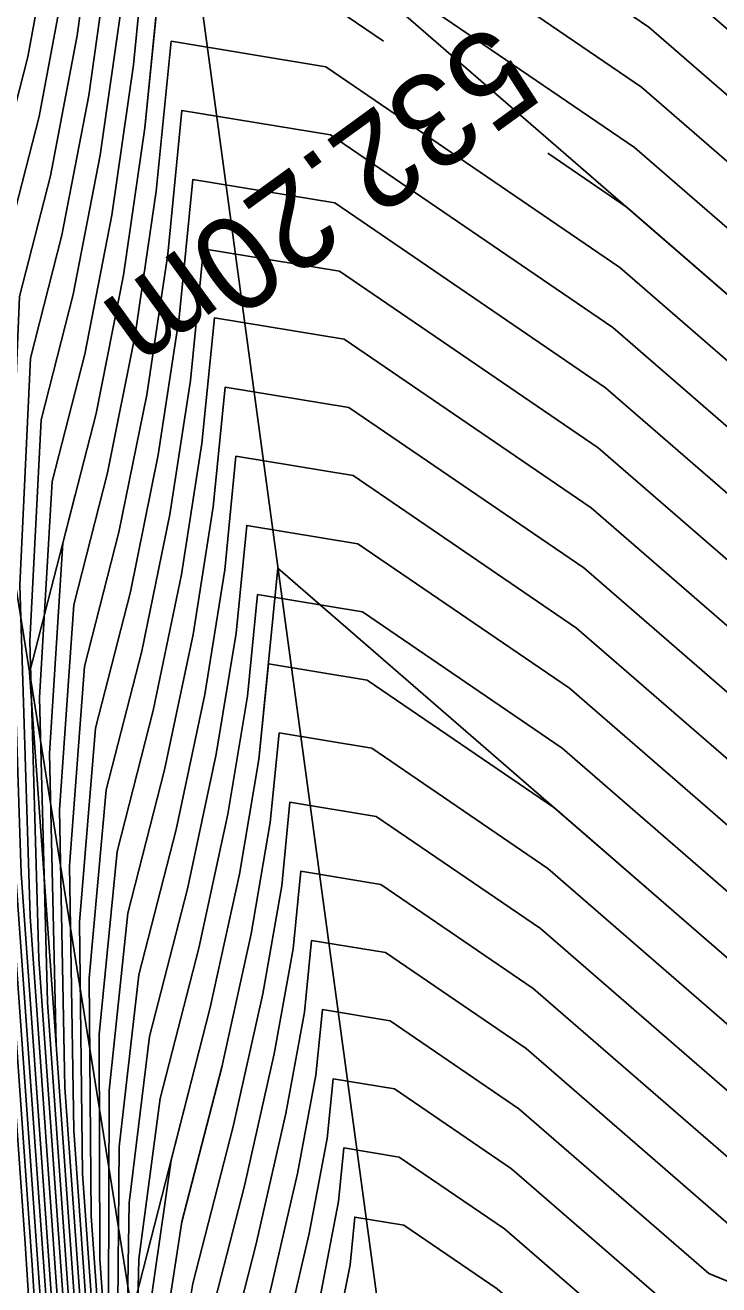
# Model space of a CAD drawing. Extents: x -866683 to -866410, y -1041951 to -1040252.
# Drawn here: x -866464.336 to -866462.114, y -1041913.857 to -1041909.824 of the extents above; entities that cross this region are included whole.
import ezdxf

# ---------------------------------------------------------------- set-up
doc = ezdxf.new("R2010")
doc.units = 0
for name, color, linetype in [('BREAKLINE', 7, 'Continuous'), ('V-VEDL', 7, 'Continuous'), ('V_po_cm', 7, 'Continuous')]:
    doc.layers.add(name, color=color, linetype=linetype)

msp = doc.modelspace()

# ---------------------------------------------------------------- linework, layer by layer
at = {"layer": 'BREAKLINE'}
for points in [[(-866488.573, -1041881.791), (-866474.022, -1041889.87), (-866470.477, -1041891.508), (-866467.312, -1041894.734), (-866465.316, -1041898.37), (-866463.007, -1041915.39), (-866458.763, -1041945.697)], [(-866461.505, -1041933.103), (-866461.806, -1041928.832), (-866463.744, -1041915.502), (-866466.191, -1041900.225), (-866466.769, -1041897.87), (-866468.011, -1041895.26), (-866470.525, -1041893.498), (-866471.281, -1041892.954)]]:
    msp.add_lwpolyline(points, dxfattribs=at)
at = {"layer": 'V-VEDL'}
for points in [[(-866464.3213, -1041911.8978), (-866464.1083, -1041911.0673), (-866464.0207, -1041910.6241), (-866463.9521, -1041910.153), (-866463.8529, -1041909.155)], [(-866456.0139, -1041911.9987), (-866456.2926, -1041911.9417), (-866456.7284, -1041912.0338), (-866457.4606, -1041912.2465), (-866458.4892, -1041912.5798), (-866459.6567, -1041912.3845), (-866460.9629, -1041911.6604), (-866463.8529, -1041909.155)], [(-866463.5263, -1041911.5623), (-866463.5872, -1041912.175), (-866463.6493, -1041912.542), (-866463.7429, -1041912.9695), (-866463.9933, -1041913.9456)], [(-866453.6171, -1041916.4043), (-866455.6514, -1041914.0403), (-866456.43, -1041913.2461), (-866456.9701, -1041912.8398), (-866457.2717, -1041912.8213), (-866457.8386, -1041912.9275), (-866458.6706, -1041913.1584), (-866459.7678, -1041913.5139), (-866460.795, -1041913.4946), (-866461.7521, -1041913.1004), (-866463.5263, -1041911.5623)], [(-866464.3213, -1041911.8978), (-866464.1509, -1041914.28), (-866464.0543, -1041915.8336), (-866463.9464, -1041917.7497), (-866463.8271, -1041920.0282), (-866463.661, -1041922.6795), (-866463.4481, -1041925.7036), (-866462.9286, -1041932.4974)]]:
    msp.add_lwpolyline(points, dxfattribs=at)
at = {"layer": 'V_po_cm'}
for points in [[(-866463.994, -1041919.6179), (-866464.1029, -1041917.5376), (-866464.2169, -1041915.5731), (-866464.3358, -1041913.7246), (-866464.4598, -1041911.992), (-866464.5119, -1041910.718), (-866464.4922, -1041909.9025), (-866464.4006, -1041909.5456), (-866464.3179, -1041909.0899), (-866464.2441, -1041908.5354), (-866464.1791, -1041907.8823), (-866463.5054, -1041907.9934), (-866462.2228, -1041908.8688), (-866460.3315, -1041910.5084), (-866458.8134, -1041911.5182), (-866457.6687, -1041911.8981), (-866456.8972, -1041911.6481), (-866456.2869, -1041911.5011), (-866455.8377, -1041911.457), (-866455.5498, -1041911.516), (-866455.0449, -1041911.9186), (-866454.3232, -1041912.6651), (-866452.446, -1041914.8455)], [(-866463.9732, -1041919.6692), (-866464.0834, -1041917.5641), (-866464.1965, -1041915.6057), (-866464.3127, -1041913.794), (-866464.4318, -1041912.1292), (-866464.4801, -1041910.8978), (-866464.4575, -1041910.1), (-866464.364, -1041909.7358), (-866464.2807, -1041909.2817), (-866464.2076, -1041908.7376), (-866464.1445, -1041908.1037), (-866463.4907, -1041908.2115), (-866462.2459, -1041909.0611), (-866460.4104, -1041910.6524), (-866458.9188, -1041911.6265), (-866457.7712, -1041911.9833), (-866456.9676, -1041911.7229), (-866456.342, -1041911.5677), (-866455.8946, -1041911.5176), (-866455.6252, -1041911.5727), (-866455.1094, -1041912), (-866454.3471, -1041912.7994), (-866452.3298, -1041915.1426)], [(-866463.9523, -1041919.7205), (-866464.0638, -1041917.5906), (-866464.1762, -1041915.6382), (-866464.2896, -1041913.8635), (-866464.4038, -1041912.2663), (-866464.4483, -1041911.0776), (-866464.4228, -1041910.2975), (-866464.3275, -1041909.926), (-866464.2436, -1041909.4735), (-866464.1711, -1041908.9398), (-866464.11, -1041908.3252), (-866463.476, -1041908.4297), (-866462.2691, -1041909.2535), (-866460.4893, -1041910.7964), (-866459.0242, -1041911.7348), (-866457.8738, -1041912.0686), (-866457.038, -1041911.7977), (-866456.3972, -1041911.6343), (-866455.9514, -1041911.5782), (-866455.7006, -1041911.6295), (-866455.1738, -1041912.0814), (-866454.3711, -1041912.9338), (-866452.2137, -1041915.4397)], [(-866463.9314, -1041919.7718), (-866464.0442, -1041917.6171), (-866464.1559, -1041915.6708), (-866464.2665, -1041913.9329), (-866464.3759, -1041912.4034), (-866464.4164, -1041911.2574), (-866464.3881, -1041910.495), (-866464.291, -1041910.1162), (-866464.2065, -1041909.6652), (-866464.1346, -1041909.142), (-866464.0754, -1041908.5467), (-866463.4613, -1041908.6479), (-866462.2922, -1041909.4459), (-866460.5683, -1041910.9404), (-866459.1296, -1041911.8431), (-866457.9764, -1041912.1538), (-866457.1084, -1041911.8725), (-866456.4524, -1041911.7008), (-866456.0083, -1041911.6388), (-866455.7761, -1041911.6863), (-866455.2383, -1041912.1627), (-866454.3951, -1041913.0681), (-866452.0976, -1041915.7367)], [(-866451.9815, -1041916.0338), (-866454.4191, -1041913.2024), (-866455.3028, -1041912.2441), (-866455.8515, -1041911.7431), (-866456.0651, -1041911.6993), (-866456.5076, -1041911.7674), (-866457.1789, -1041911.9473), (-866458.0789, -1041912.239), (-866459.2351, -1041911.9514), (-866460.6472, -1041911.0844), (-866462.3153, -1041909.6382), (-866463.4466, -1041908.8661), (-866464.0408, -1041908.7681), (-866464.0981, -1041909.3442), (-866464.1693, -1041909.857), (-866464.2544, -1041910.3064), (-866464.3535, -1041910.6925), (-866464.3846, -1041911.4372), (-866464.3479, -1041912.5405), (-866464.2433, -1041914.0023), (-866464.1356, -1041915.7034), (-866464.0247, -1041917.6436), (-866463.9105, -1041919.8231)], [(-866463.8897, -1041919.8744), (-866464.0051, -1041917.6701), (-866464.1153, -1041915.7359), (-866464.2202, -1041914.0717), (-866464.32, -1041912.6776), (-866464.3528, -1041911.617), (-866464.3188, -1041910.89), (-866464.2179, -1041910.4967), (-866464.1322, -1041910.0488), (-866464.0616, -1041909.5464), (-866464.0062, -1041908.9896), (-866463.4319, -1041909.0843), (-866462.3385, -1041909.8306), (-866460.7261, -1041911.2284), (-866459.3405, -1041912.0596), (-866458.1815, -1041912.3242), (-866457.2493, -1041912.0221), (-866456.5628, -1041911.834), (-866456.122, -1041911.7599), (-866455.9269, -1041911.7998), (-866455.3673, -1041912.3255), (-866454.443, -1041913.3368), (-866451.8653, -1041916.3308)], [(-866463.8688, -1041919.9257), (-866463.9855, -1041917.6967), (-866464.0949, -1041915.7685), (-866464.1971, -1041914.1412), (-866464.292, -1041912.8147), (-866464.321, -1041911.7968), (-866464.2841, -1041911.0875), (-866464.1814, -1041910.6869), (-866464.095, -1041910.2406), (-866464.0251, -1041909.7486), (-866463.9717, -1041909.2111), (-866463.4172, -1041909.3025), (-866462.3616, -1041910.023), (-866460.805, -1041911.3724), (-866459.4459, -1041912.1679), (-866458.2841, -1041912.4094), (-866457.3197, -1041912.0969), (-866456.618, -1041911.9006), (-866456.1789, -1041911.8205), (-866456.0024, -1041911.8566), (-866455.4317, -1041912.4068), (-866454.467, -1041913.4711), (-866451.7492, -1041916.6279)], [(-866451.6331, -1041916.9249), (-866454.491, -1041913.6054), (-866455.4962, -1041912.4882), (-866456.0778, -1041911.9134), (-866456.2357, -1041911.8811), (-866456.6732, -1041911.9672), (-866457.3901, -1041912.1717), (-866458.3867, -1041912.4946), (-866459.5513, -1041912.2762), (-866460.884, -1041911.5164), (-866462.3847, -1041910.2153), (-866463.4024, -1041909.5207), (-866463.9371, -1041909.4325), (-866463.9886, -1041909.9508), (-866464.0579, -1041910.4324), (-866464.1448, -1041910.8771), (-866464.2495, -1041911.285), (-866464.2892, -1041911.9766), (-866464.264, -1041912.9518), (-866464.174, -1041914.2106), (-866464.0746, -1041915.8011), (-866463.9659, -1041917.7232), (-866463.8479, -1041919.9769)], [(-866463.9971, -1041910.462), (-866463.9521, -1041910.153), (-866463.9025, -1041909.654), (-866463.3877, -1041909.7389), (-866463.1882, -1041909.8751)], [(-866463.8062, -1041920.0795), (-866463.9268, -1041917.7762), (-866464.034, -1041915.8662), (-866464.1278, -1041914.3495), (-866464.2081, -1041913.226), (-866464.2256, -1041912.3362), (-866464.1801, -1041911.68), (-866464.0717, -1041911.2575), (-866463.9836, -1041910.8159), (-866463.9156, -1041910.3552), (-866463.8679, -1041909.8755), (-866463.373, -1041909.9571), (-866462.431, -1041910.6001), (-866461.0418, -1041911.8044), (-866459.7621, -1041912.4928), (-866458.5918, -1041912.665), (-866457.531, -1041912.3213), (-866456.7835, -1041912.1004), (-866456.3494, -1041912.0022), (-866456.2287, -1041912.0269), (-866455.6252, -1041912.6509), (-866454.5389, -1041913.8741), (-866451.4009, -1041917.519)], [(-866463.7853, -1041920.1308), (-866463.9072, -1041917.8027), (-866464.0137, -1041915.8988), (-866464.1046, -1041914.4189), (-866464.1802, -1041913.3631), (-866464.1938, -1041912.516), (-866464.1455, -1041911.8775), (-866464.0352, -1041911.4477), (-866463.9464, -1041911.0077), (-866463.8791, -1041910.5574), (-866463.8334, -1041910.0969), (-866463.3583, -1041910.1753), (-866462.4541, -1041910.7924), (-866461.1207, -1041911.9484), (-866459.8675, -1041912.601), (-866458.6944, -1041912.7503), (-866457.6014, -1041912.3961), (-866456.8387, -1041912.1669), (-866456.4063, -1041912.0628), (-866456.3041, -1041912.0837), (-866455.6896, -1041912.7323), (-866454.5629, -1041914.0085), (-866451.2847, -1041917.8161)], [(-866462.6617, -1041910.2344), (-866462.4079, -1041910.4077), (-866460.9629, -1041911.6604), (-866459.7349, -1041912.3411)], [(-866463.7645, -1041920.1821), (-866463.8876, -1041917.8293), (-866463.9933, -1041915.9313), (-866464.0815, -1041914.4883), (-866464.1522, -1041913.5002), (-866464.162, -1041912.6958), (-866464.1108, -1041912.075), (-866463.9987, -1041911.638), (-866463.9093, -1041911.1995), (-866463.8427, -1041910.7596), (-866463.7988, -1041910.3184), (-866463.3436, -1041910.3934), (-866462.4773, -1041910.9848), (-866461.1996, -1041912.0924), (-866459.9729, -1041912.7093), (-866458.7969, -1041912.8355), (-866457.6718, -1041912.4709), (-866456.8939, -1041912.2335), (-866456.4631, -1041912.1234), (-866456.3795, -1041912.1405), (-866455.7541, -1041912.8136), (-866454.5868, -1041914.1428), (-866451.1686, -1041918.1132)], [(-866451.0525, -1041918.4102), (-866454.6108, -1041914.2771), (-866455.8186, -1041912.895), (-866456.455, -1041912.1973), (-866456.52, -1041912.184), (-866456.9491, -1041912.3001), (-866457.7423, -1041912.5457), (-866458.8995, -1041912.9207), (-866460.0783, -1041912.8176), (-866461.2786, -1041912.2364), (-866462.5004, -1041911.1772), (-866463.3289, -1041910.6116), (-866463.7642, -1041910.5399), (-866463.8062, -1041910.9618), (-866463.8721, -1041911.3913), (-866463.9621, -1041911.8282), (-866464.0761, -1041912.2725), (-866464.1302, -1041912.8756), (-866464.1243, -1041913.6373), (-866464.0584, -1041914.5578), (-866463.973, -1041915.9639), (-866463.8681, -1041917.8558), (-866463.7436, -1041920.2334)], [(-866463.7227, -1041920.2847), (-866463.8485, -1041917.8823), (-866463.9527, -1041915.9965), (-866464.0353, -1041914.6272), (-866464.0963, -1041913.7744), (-866464.0983, -1041913.0554), (-866464.0414, -1041912.47), (-866463.9256, -1041912.0184), (-866463.835, -1041911.5831), (-866463.7697, -1041911.164), (-866463.7296, -1041910.7613), (-866463.3142, -1041910.8298), (-866462.5235, -1041911.3695), (-866461.3575, -1041912.3804), (-866460.1837, -1041912.9259), (-866459.0021, -1041913.0059), (-866457.8127, -1041912.6205), (-866457.0043, -1041912.3667), (-866456.5769, -1041912.2446), (-866456.5304, -1041912.2541), (-866455.883, -1041912.9764), (-866454.6348, -1041914.4115), (-866450.9364, -1041918.7073)], [(-866463.7019, -1041920.3359), (-866463.8289, -1041917.9088), (-866463.9324, -1041916.029), (-866464.0122, -1041914.6966), (-866464.0683, -1041913.9116), (-866464.0665, -1041913.2352), (-866464.0068, -1041912.6675), (-866463.889, -1041912.2086), (-866463.7978, -1041911.7748), (-866463.7332, -1041911.3662), (-866463.695, -1041910.9828), (-866463.2995, -1041911.048), (-866462.5467, -1041911.5619), (-866461.4364, -1041912.5244), (-866460.2891, -1041913.0342), (-866459.1046, -1041913.0911), (-866457.8831, -1041912.6953), (-866457.0595, -1041912.4333), (-866456.6337, -1041912.3051), (-866456.6058, -1041912.3108), (-866455.9475, -1041913.0577), (-866454.6587, -1041914.5458), (-866450.8202, -1041919.0043)], [(-866463.681, -1041920.3872), (-866463.8094, -1041917.9353), (-866463.912, -1041916.0616), (-866463.989, -1041914.766), (-866464.0404, -1041914.0487), (-866464.0347, -1041913.415), (-866463.9721, -1041912.865), (-866463.8525, -1041912.3988), (-866463.7607, -1041911.9666), (-866463.6967, -1041911.5684), (-866463.6605, -1041911.2043), (-866463.2848, -1041911.2662), (-866462.5698, -1041911.7543), (-866461.5153, -1041912.6684), (-866460.3945, -1041913.1424), (-866459.2072, -1041913.1763), (-866457.9535, -1041912.7701), (-866457.1147, -1041912.4999), (-866456.6906, -1041912.3657), (-866456.6813, -1041912.3676), (-866456.012, -1041913.1391), (-866454.6827, -1041914.6801), (-866450.7041, -1041919.3014)], [(-866464.1021, -1041915.0639), (-866464.1509, -1041914.28), (-866464.2361, -1041913.0889), (-866464.2574, -1041912.1564), (-866464.2148, -1041911.4825), (-866464.175, -1041911.3273)], [(-866459.3604, -1041913.2779), (-866460.5167, -1041913.2562), (-866461.5943, -1041912.8124), (-866462.5929, -1041911.9466), (-866463.2701, -1041911.4844), (-866463.6259, -1041911.4257), (-866463.6602, -1041911.7706), (-866463.7236, -1041912.1584), (-866463.816, -1041912.589), (-866463.9374, -1041913.0625), (-866464.0029, -1041913.5948), (-866464.0124, -1041914.1858), (-866463.9659, -1041914.8355), (-866463.8917, -1041916.0942), (-866463.7898, -1041917.9618), (-866463.6601, -1041920.4385)], [(-866463.6393, -1041920.4898), (-866463.7702, -1041917.9884), (-866463.8714, -1041916.1267), (-866463.9428, -1041914.9049), (-866463.9845, -1041914.3229), (-866463.9711, -1041913.7746), (-866463.9028, -1041913.2601), (-866463.7794, -1041912.7793), (-866463.6864, -1041912.3502), (-866463.6237, -1041911.9728), (-866463.5913, -1041911.6472), (-866463.2554, -1041911.7026), (-866462.6161, -1041912.139), (-866461.6732, -1041912.9564), (-866460.6559, -1041913.3754), (-866459.5641, -1041913.3959)], [(-866463.9509, -1041914.2954), (-866463.9393, -1041913.9544), (-866463.8681, -1041913.4576), (-866463.7429, -1041912.9695), (-866463.6493, -1041912.542), (-866463.5872, -1041912.175), (-866463.5567, -1041911.8687), (-866463.2407, -1041911.9208), (-866462.6392, -1041912.3314), (-866462.1448, -1041912.7599)], [(-866458.9433, -1041913.2987), (-866459.9715, -1041913.6319), (-866460.9341, -1041913.6138), (-866461.831, -1041913.2444), (-866462.6623, -1041912.5237), (-866463.226, -1041912.139), (-866463.5222, -1041912.0901), (-866463.5507, -1041912.3772), (-866463.6121, -1041912.7337), (-866463.7063, -1041913.1597), (-866463.8334, -1041913.6551), (-866463.9075, -1041914.1342), (-866463.9285, -1041914.5971), (-866463.8966, -1041915.0438), (-866463.8308, -1041916.1919), (-866463.7311, -1041918.0414), (-866463.5975, -1041920.5924)], [(-866463.5766, -1041920.6437), (-866463.7115, -1041918.0679), (-866463.8104, -1041916.2244), (-866463.8735, -1041915.1132), (-866463.9006, -1041914.7342), (-866463.8757, -1041914.314), (-866463.7987, -1041913.8526), (-866463.6698, -1041913.3499), (-866463.575, -1041912.9255), (-866463.5142, -1041912.5794), (-866463.4876, -1041912.3116), (-866463.2113, -1041912.3572), (-866462.6855, -1041912.7161), (-866461.91, -1041913.3884), (-866461.0732, -1041913.733), (-866460.1752, -1041913.7499), (-866459.216, -1041913.4391), (-866458.3956, -1041913.2429), (-866457.7139, -1041913.1615), (-866457.171, -1041913.1948), (-866456.1988, -1041913.9262), (-866454.7973, -1041915.3557), (-866452.9665, -1041917.4833), (-866451.6335, -1041919.0324)], [(-866450.0304, -1041921.0569), (-866454.4154, -1041915.9609), (-866456.0982, -1041914.2487), (-866457.2714, -1041913.3723), (-866457.935, -1041913.3316), (-866458.6741, -1041913.4007), (-866459.4888, -1041913.5794), (-866460.379, -1041913.8679), (-866461.2123, -1041913.8522), (-866461.9889, -1041913.5324), (-866462.7086, -1041912.9085), (-866463.1966, -1041912.5753), (-866463.453, -1041912.5331), (-866463.4777, -1041912.7816), (-866463.5378, -1041913.1173), (-866463.6333, -1041913.5401), (-866463.7641, -1041914.0501), (-866463.8439, -1041914.4938), (-866463.8726, -1041914.8713), (-866463.8503, -1041915.1826), (-866463.7901, -1041916.257), (-866463.6919, -1041918.0944), (-866463.5558, -1041920.6949)], [(-866463.6724, -1041918.121), (-866463.7698, -1041916.2896), (-866463.8272, -1041915.2521), (-866463.8447, -1041915.0084), (-866463.812, -1041914.6736), (-866463.7294, -1041914.2476), (-866463.5967, -1041913.7303), (-866463.5007, -1041913.3091), (-866463.4412, -1041912.9838), (-866463.4184, -1041912.7545), (-866463.1819, -1041912.7935), (-866462.7317, -1041913.1008), (-866462.0678, -1041913.6764), (-866461.3515, -1041913.9714), (-866460.5827, -1041913.9859), (-866459.7615, -1041913.7198), (-866458.9526, -1041913.5584), (-866458.1561, -1041913.5017), (-866457.3719, -1041913.5498), (-866456.1332, -1041914.4138), (-866454.4399, -1041916.0938), (-866450.1444, -1041921.0858)], [(-866463.6528, -1041918.1475), (-866463.7495, -1041916.3221), (-866463.8041, -1041915.3215), (-866463.8167, -1041915.1455), (-866463.7802, -1041914.8534), (-866463.6947, -1041914.4451), (-866463.5602, -1041913.9206), (-866463.4635, -1041913.5009), (-866463.4048, -1041913.186), (-866463.3839, -1041912.976), (-866463.1672, -1041913.0117), (-866462.7549, -1041913.2932), (-866462.1467, -1041913.8204), (-866461.4906, -1041914.0906), (-866460.7864, -1041914.1039), (-866460.0342, -1041913.8601), (-866459.2312, -1041913.7161), (-866458.3772, -1041913.6718), (-866457.4723, -1041913.7273), (-866456.1681, -1041914.5789), (-866454.4645, -1041916.2267), (-866450.2585, -1041921.1147)], [(-866450.3725, -1041921.1436), (-866454.489, -1041916.3596), (-866456.203, -1041914.744), (-866457.5728, -1041913.9048), (-866458.5983, -1041913.8419), (-866459.5097, -1041913.8738), (-866460.307, -1041914.0005), (-866460.9901, -1041914.2219), (-866461.6297, -1041914.2098), (-866462.2257, -1041913.9644), (-866462.778, -1041913.4856), (-866463.1525, -1041913.2299), (-866463.3493, -1041913.1975), (-866463.3683, -1041913.3882), (-866463.4264, -1041913.6927), (-866463.5237, -1041914.1108), (-866463.6601, -1041914.6426), (-866463.7484, -1041915.0332), (-866463.7887, -1041915.2826), (-866463.781, -1041915.3909), (-866463.7291, -1041916.3547), (-866463.6332, -1041918.174)], [(-866463.6136, -1041918.2005), (-866463.7088, -1041916.3873), (-866463.7579, -1041915.4603), (-866463.7608, -1041915.4197), (-866463.7166, -1041915.213), (-866463.6254, -1041914.8401), (-866463.4871, -1041914.301), (-866463.3892, -1041913.8844), (-866463.3318, -1041913.5904), (-866463.3147, -1041913.4189), (-866463.1378, -1041913.4481), (-866462.8011, -1041913.6779), (-866462.3046, -1041914.1084), (-866461.7688, -1041914.3291), (-866461.1939, -1041914.3399), (-866460.5797, -1041914.1408), (-866459.7882, -1041914.0316), (-866458.8194, -1041914.0121), (-866457.6732, -1041914.0823), (-866456.238, -1041914.9091), (-866454.5136, -1041916.4925), (-866450.4865, -1041921.1725)], [(-866463.5914, -1041918.2787), (-866463.6829, -1041916.4704), (-866463.7246, -1041915.5523), (-866463.7165, -1041915.5245), (-866463.6669, -1041915.3335), (-866463.5758, -1041914.9793), (-866463.4431, -1041914.4621), (-866463.3496, -1041914.0665), (-866463.2953, -1041913.7926), (-866463.2801, -1041913.6404), (-866463.1231, -1041913.6663), (-866462.8243, -1041913.8703), (-866462.3835, -1041914.2524), (-866461.9079, -1041914.4483), (-866461.3976, -1041914.4579), (-866460.8524, -1041914.2812), (-866460.0667, -1041914.1893), (-866459.0405, -1041914.1822), (-866457.7737, -1041914.2598), (-866456.2729, -1041915.0742), (-866454.5381, -1041916.6254), (-866450.6006, -1041921.2014)]]:
    msp.add_lwpolyline(points, dxfattribs=at)

# ---------------------------------------------------------------- texts
msp.add_text('532.20m', height=0.3, rotation=215.9624, dxfattribs=at).set_placement((-866462.8423, -1041909.8095))

doc.saveas('drawing.dxf')
